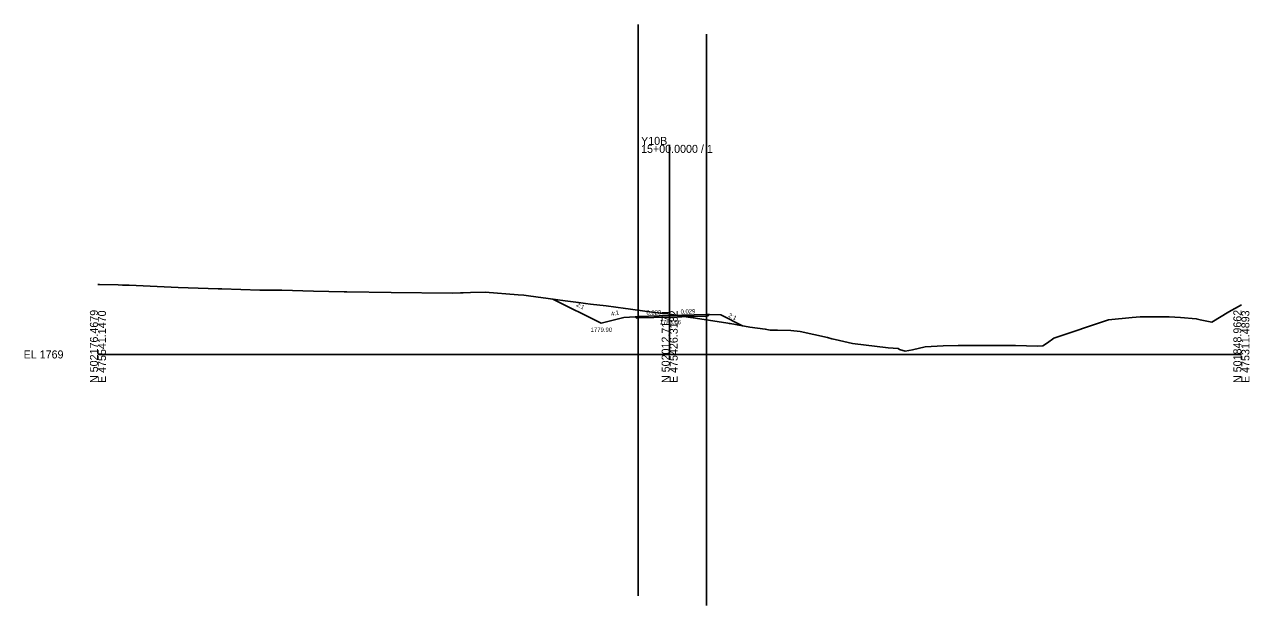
# Model space of a CAD drawing. Extents: x -26 to 1803, y -10 to 9558.
# Drawn here: x -25.7 to 402.8, y 4912.1 to 5115.5 of the extents above; entities that cross this region are included whole.
import ezdxf

# ---------------------------------------------------------------- set-up
doc = ezdxf.new("R2010")
doc.units = 0
for name, color, linetype in [('Exist Cross Section Cell', 7, 'Continuous'), ('Exist XS Center Line Elevation Label', 7, 'Continuous'), ('Exist XS Ground Line', 7, 'Continuous'), ('Prop XS Ditch Slope Text', 7, 'Continuous'), ('Prop XS Ditch Standard Text', 7, 'Continuous'), ('Prop XS Dump Level', 7, 'Continuous'), ('Prop XS Earthwork Shape', 7, 'Continuous'), ('Prop XS EOT Tick Mark', 7, 'Continuous'), ('Prop XS Finish Grade', 7, 'Continuous'), ('Prop XS Finish Grade Earthwork', 7, 'Continuous'), ('Prop XS Finish Grade Pavement', 7, 'Continuous'), ('Prop XS Hydro Typical Ditch Data', 7, 'Continuous'), ('Prop XS Pvmt Edge Slope', 7, 'Continuous'), ('Prop XS SE Text', 7, 'Continuous'), ('Prop XS Shoulder Borrow Shape', 7, 'Continuous'), ('Prop XS Side Slope Text', 7, 'Continuous'), ('Prop XS Subgrade Earthwork', 7, 'Continuous'), ('Scratch_Level_2', 7, 'Continuous')]:
    doc.layers.add(name, color=color, linetype=linetype)

msp = doc.modelspace()

# ---------------------------------------------------------------- linework, layer by layer
at = {"layer": 'Exist Cross Section Cell'}
for p, q in [((200, 5000), (200, 5073.36)), ((0, 5000), (200, 5000)), ((200, 5000), (400, 5000))]:
    msp.add_line(p, q, dxfattribs=at)
at = {"layer": 'Exist XS Ground Line'}
msp.add_lwpolyline([(0, 5024.44), (0.49, 5024.45), (7.08, 5024.38), (8.6, 5024.3), (10.88, 5024.21), (28.01, 5023.43), (42, 5022.98), (43.36, 5022.93), (56.61, 5022.53), (64.3, 5022.46), (75.4, 5022.17), (86.15, 5021.89), (86.58, 5021.9), (87.07, 5021.9), (102.59, 5021.73), (123.9, 5021.48), (126.84, 5021.57), (127.76, 5021.62), (130.36, 5021.67), (135.51, 5021.74), (146.99, 5020.88), (149.04, 5020.76), (150.67, 5020.54), (160.12, 5019.2), (163.4, 5018.77), (168.09, 5018.17), (170.58, 5017.85), (172.33, 5017.62), (177.77, 5016.96), (184.55, 5016.09), (185.51, 5015.96), (192.13, 5015.07), (196.77, 5014.48), (199.31, 5014.17), (200, 5014.06), (202.93, 5013.61), (206.49, 5013.08), (208.98, 5012.74), (220.35, 5010.93), (220.85, 5010.85), (221.2, 5010.79), (228.03, 5009.6), (233.41, 5008.87), (235.21, 5008.54), (237.77, 5008.5), (242.39, 5008.34), (245.63, 5008.05), (255.19, 5005.9), (256.75, 5005.42), (257.85, 5005.19), (263.93, 5003.85), (276.4, 5002.33), (279.97, 5002.1), (280.45, 5001.69), (282.38, 5001.13), (284.91, 5001.58), (289.39, 5002.63), (295.64, 5003.04), (300.92, 5003.17), (318.33, 5003.11), (320.99, 5003.08), (328.72, 5002.92), (330.57, 5003.02), (332.15, 5004.11), (334.36, 5005.68), (353.55, 5012.14), (361.81, 5012.93), (364.57, 5013.18), (367.93, 5013.14), (374.68, 5013.12), (378.71, 5012.88), (384.22, 5012.5), (385.63, 5012.17), (389.7, 5011.26), (395.58, 5014.9), (400, 5017.39)], dxfattribs=at)
at = {"layer": 'Prop XS Dump Level'}
for p, q in [((200, 5013.62), (212.9, 5013.99)), ((189, 5013.3), (200, 5013.62))]:
    msp.add_line(p, q, dxfattribs=at)
at = {"layer": 'Prop XS Earthwork Shape'}
for points in [[(187.97, 5013.22), (184, 5012.9), (176, 5010.9), (159.12, 5019.34), (160.12, 5019.2), (163.4, 5018.77), (168.09, 5018.17), (170.58, 5017.85), (172.33, 5017.62), (177.77, 5016.96), (184.55, 5016.09), (185.51, 5015.96), (192.13, 5015.07), (196.77, 5014.48), (199.31, 5014.17), (200, 5014.06), (202.93, 5013.61), (205.48, 5013.23), (200, 5013.07), (189, 5012.76), (188.44, 5012.74)], [(213.92, 5013.95), (217.9, 5013.83), (225.48, 5010.04), (221.2, 5010.79), (220.85, 5010.85), (220.35, 5010.93), (208.98, 5012.74), (206.49, 5013.08), (205.48, 5013.23), (212.9, 5013.45), (213.42, 5013.46)]]:
    msp.add_lwpolyline(points, close=True, dxfattribs=at)
at = {"layer": 'Prop XS EOT Tick Mark'}
for p, q in [((189, 5013.3), (189, 5014.3)), ((212.9, 5013.99), (212.9, 5014.99))]:
    msp.add_line(p, q, dxfattribs=at)
at = {"layer": 'Prop XS Finish Grade'}
for p, q in [((212.9, 5013.99), (213.92, 5013.95)), ((189, 5013.3), (187.97, 5013.22))]:
    msp.add_line(p, q, dxfattribs=at)
at = {"layer": 'Prop XS Finish Grade Earthwork'}
for p, q in [((176, 5010.9), (159.12, 5019.34)), ((213.92, 5013.95), (217.9, 5013.83)), ((184, 5012.9), (176, 5010.9)), ((187.97, 5013.22), (184, 5012.9)), ((225.48, 5010.04), (217.9, 5013.83))]:
    msp.add_line(p, q, dxfattribs=at)
at = {"layer": 'Prop XS Finish Grade Pavement'}
for p, q in [((200, 5013.62), (212.9, 5013.99)), ((189, 5013.3), (200, 5013.62))]:
    msp.add_line(p, q, dxfattribs=at)
at = {"layer": 'Prop XS Hydro Typical Ditch Data'}
for p, q in [((176, 5010.9), (159.12, 5019.34)), ((184, 5012.9), (176, 5010.9)), ((221.42, 5012.07), (217.9, 5013.83))]:
    msp.add_line(p, q, dxfattribs=at)
at = {"layer": 'Prop XS Pvmt Edge Slope'}
for p, q in [((212.9, 5013.99), (213.42, 5013.46)), ((189, 5013.3), (188.44, 5012.74))]:
    msp.add_line(p, q, dxfattribs=at)
at = {"layer": 'Prop XS Shoulder Borrow Shape'}
for points in [[(212.9, 5013.99), (213.92, 5013.95), (213.42, 5013.46)], [(189, 5013.3), (187.97, 5013.22), (188.44, 5012.74)]]:
    msp.add_lwpolyline(points, close=True, dxfattribs=at)
at = {"layer": 'Prop XS Subgrade Earthwork'}
for p, q in [((213.42, 5013.46), (213.92, 5013.95)), ((188.44, 5012.74), (187.97, 5013.22)), ((189, 5012.76), (188.44, 5012.74)), ((200, 5013.07), (189, 5012.76)), ((212.9, 5013.45), (200, 5013.07)), ((212.9, 5013.45), (213.42, 5013.46))]:
    msp.add_line(p, q, dxfattribs=at)
at = {"layer": 'Scratch_Level_2'}
for p, q in [((189, 5115.49), (189, 4915.49)), ((212.9, 5112.12), (212.9, 4912.12))]:
    msp.add_line(p, q, dxfattribs=at)

# ---------------------------------------------------------------- texts
at = {"layer": 'Exist Cross Section Cell'}
for s, p in [('Y10B', (190, 5073.36)), ('15+00.0000 / 1', (190, 5070.56)), ('EL 1769', (-26, 4998.6))]:
    msp.add_text(s, height=2.8, dxfattribs=at).set_placement(p)
for s, p in [('N 502176.4679', (0, 4990)), ('E 475541.1470', (2.8, 4990)), ('N 502012.7171', (200, 4990)), ('E 475426.3182', (202.8, 4990)), ('N 501848.9662', (400, 4990)), ('E 475311.4893', (402.8, 4990))]:
    msp.add_text(s, height=2.8, rotation=90, dxfattribs=at).set_placement(p)
at = {"layer": 'Exist XS Center Line Elevation Label'}
msp.add_text('1783.06', height=1.5, dxfattribs=at).set_placement((196.49, 5010.56))
at = {"layer": 'Prop XS Ditch Slope Text'}
msp.add_text('4:1', height=1.5, rotation=14.0362, dxfattribs=at).set_placement((179.64, 5013.35))
at = {"layer": 'Prop XS Ditch Standard Text'}
msp.add_text('1779.90', height=1.5, dxfattribs=at).set_placement((172.37, 5007.9))
at = {"layer": 'Prop XS Dump Level'}
for p in [(217.9, 5013.79), (184, 5012.86)]:
    msp.add_text('Case1', height=0.04, dxfattribs=at).set_placement(p)
at = {"layer": 'Prop XS SE Text'}
for p in [(191.89, 5013.88), (203.84, 5014.23)]:
    msp.add_text('0.029', height=1.5, rotation=1.6493, dxfattribs=at).set_placement(p)
at = {"layer": 'Prop XS Side Slope Text'}
for p in [(167.17, 5016.99), (220.4, 5013.21)]:
    msp.add_text('2:1', height=1.5, rotation=333.4349, dxfattribs=at).set_placement(p)

doc.saveas('drawing.dxf')
